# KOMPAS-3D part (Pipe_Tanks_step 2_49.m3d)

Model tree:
1. X Axis
2. Y Axis
3. Z Axis  (labels: Pipe Dn 50)
     Òîëùèíà ñòåíêè 1 = 1

Referenced files in C:\Documents and Settings\kashirsky\Мои документы\Camtasia Studio\Pipelines3D\Tanks\: Tanks_step 2.a3d
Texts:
  Pipe Dn 50
  Steel ASTM A295
  Three Point Plane
  Plane at Angle
  Line and Point Plane
  Axis through Two Vertices
  Axis of Feature
  Axis of Conical Surface
  Axis through Edge
  Trim by Surface
  Trim by Sketch
  Feature with No History
  Intersection Axis of Two Planes
  Two Line Plane
  Line and Face Plane
  Bend by line
  Hole in sheet body
  Cut in sheet body
  Point in CM
  Linear Dimension from Line to Point
  Surface Finish Symbol
  Geometric Tolerance Symbol
  Leader #1
  Leader #2
  Leader #3
  Shape Deviations and Datum
  Node point number
  Mark of coordination axis
  Node point designation
  Mark/Reference designation with leader
  Mark/reference designation on line
  Mark/Reference designation without leader
  Plane of section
